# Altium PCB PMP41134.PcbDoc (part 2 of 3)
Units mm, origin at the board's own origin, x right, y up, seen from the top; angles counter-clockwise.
Board outline 252.04 x 132.61 mm, 6 copper layers (Top Layer, Layer 1, Layer 2, Layer 3, Layer 4, Bottom Layer), stack 2.208 mm thick; 221 components, 92 nets, 680 pads, 1197 vias.
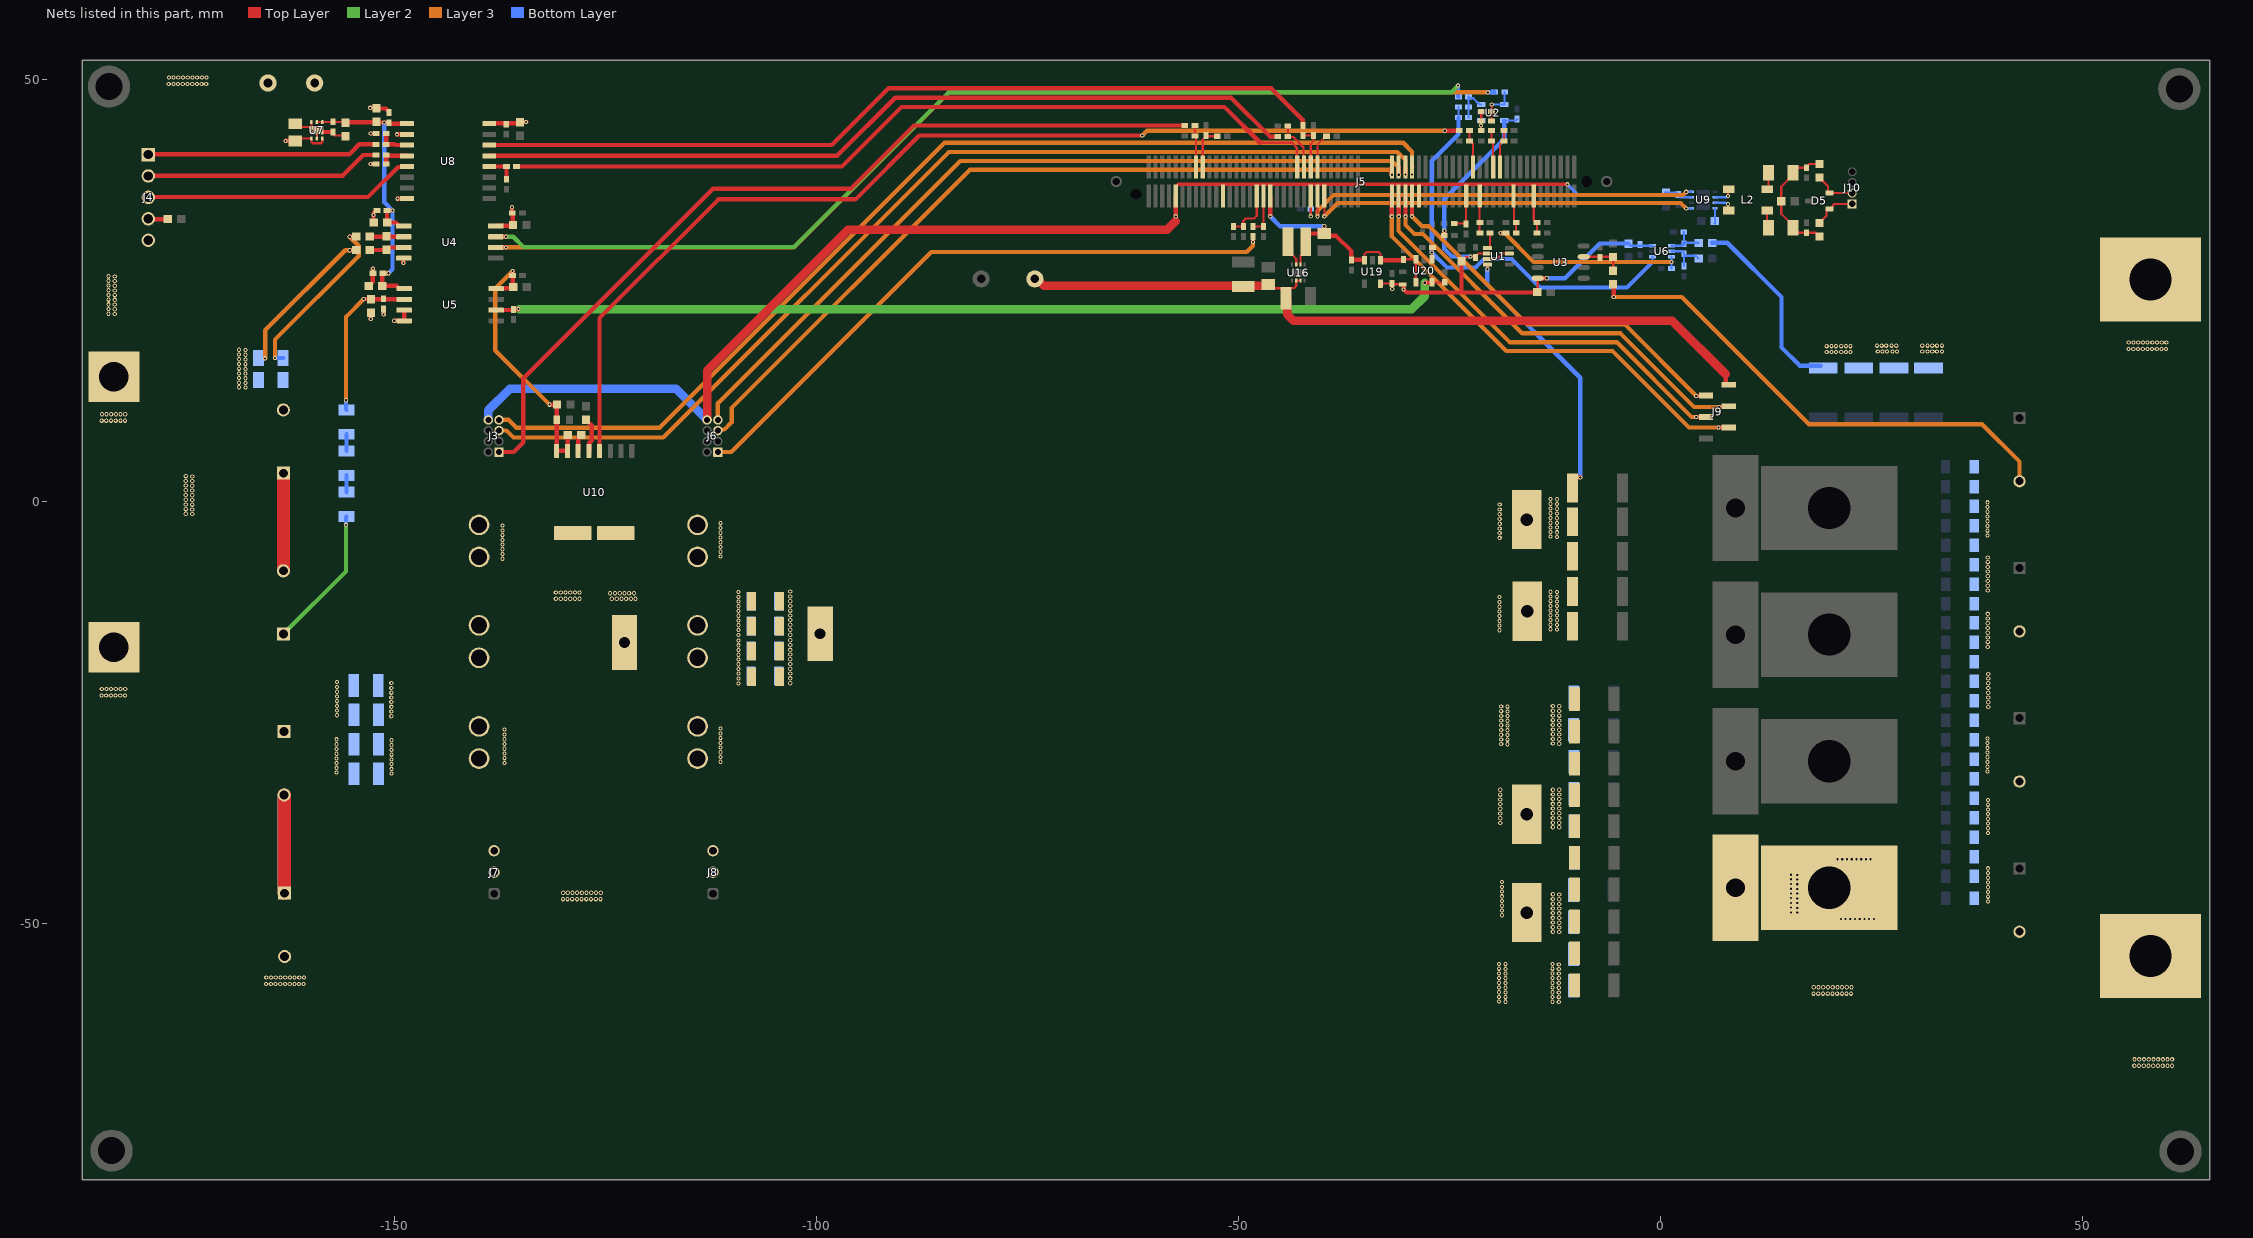
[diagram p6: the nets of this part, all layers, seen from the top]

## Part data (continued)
C128 C129: library part CMP-0009211-2, "CAP, CERM, 47 uF, 16 V, +/- 10%, X5R, 1210", Cap_Case=1210, Manufacturer=MuRata, Supplier Part Number 1=GRM32ER61C476KE15L-ND, TempCo=X5R, Tolerance_%=10%, Value1=Unknown, Value2=16V, ValueDisplayed=47uF
C131: library part CMP-0085852-1, "CAP, CERM, 22 µF, 16 V,+/- 10%, X5R, 0805", Cap_Case=0805, Manufacturer="Samsung Electro-Mechanics", TempCo=X5R, Tolerance_%=10%, Value2=16V, ValueDisplayed=22µF
C140 C141: library part CMP-0006297-2, "CAP, CERM, 0.1 uF, 50 V, +/- 10%, X7R, 0402", Alternate Manufacturer="Wurth Elektronik", Alternate PartNumber=885012205037, Cap_Case=0402, Manufacturer=TDK, Supplier Part Number 1=445-5932-1-ND, TempCo=X7R, Tolerance_%=10%, Value1="0.039064 ohm", Value2=50V, ValueDisplayed=0.1uF
C142: library part CMP-0076705-3, "CAP, CERM, 1 µF, 25 V,+/- 10%, X7R, AEC-Q200 Grade 1, 0603", Cap_Case=1.6x0.8x0.8mm, Manufacturer=TDK, Supplier Part Number 1=445-6931-1-ND, TempCo=X7R, Tolerance_%=10%, Value2=25V, ValueDisplayed=1µF
D5: library part CMP-0005919-3, "Diode, TVS, Bi, 24 V, SOT-23", Manufacturer="ON Semiconductor", Value1=350W
HV_SW1 HV_SW1 HV_SW2 HV_SW2 HVBUS HVBUS HVBUS1 HVBUS2 PGND PGND PGND1 PGND2: library part CMP-0055026-1, Manufacturer=Mill-Max, Supplier Part Number 1=0312-015153427100-ND
J3 J6: library part CMP-0097755-1, "Conn Socket Strip SKT 8 POS 1.27mm Solder ST Thru-Hole", Current_A=1A, Manufacturer=Harwin, Operating Temperature Range="-40°C to +105°C"
J4: library part CMP-0054800-1, "Header, 2.54 mm, 5x1, Gold, R/A, TH", Color=Black, Manufacturer="Wurth Elektronik", Supplier Part Number 1=732-5338-ND
J5: library part CMP-0003814-2, "C2000 controlCARD-120HSEC connector, SMT", Manufacturer=Samtec
J7 J8: library part CMP-0076709-1, "Receptacle, 2.54mm, 3x1, Gold, TH", Color=Black, Manufacturer=Mill-Max, Supplier Part Number 1=575-8014100310001000
J9: library part CMP-0054652-1, "Receptacle, 1.27mm, 6x1, Gold, SMT", Color=Black, Manufacturer="Sullins Connector Solutions", Supplier Part Number 1=S9005E-06-ND
J10: library part CMP-0054569-1, "Header, 50mil, 4x1, Gold, TH", Manufacturer="Sullins Connector Solutions", Supplier Part Number 1=S9014E-04-ND
L2: library part CMP-0062430-2, "Inductor, Ferrite, 100 uH, 0.15 A, 2 ohm, SMD", Manufacturer=TDK, Supplier Part Number 1=445-3959-1-ND, Value1="2 ohm", Value2=0.15A, ValueDisplayed=100uH
L7: library part CMP-0087867-1, "2.2µH Shielded Molded Inductor 2.4A 67mOhm Max 2-SMD", Manufacturer="Wurth Electronics"
R1 R2 R4 R7 R16 R46 R49 R50 R54: library part CMP-0015817-2, "RES, 0.0005, 1%, 2 W, 2512", Manufacturer="Stackpole Electronics Inc", Power_W=3W, TempCo=ppm/C, Tolerance_%=1%, Value2=2W, Value_Code=1L000, ValueDisplayed=0.0005
R3: library part CMP-0022438-1, "RES, 47.0 k, 1%, 0.1 W, AEC-Q200 Grade 0, 0603", Manufacturer=Vishay-Dale, Power_W=100mW, Supplier Part Number 1=541-47.0KHCT-ND, TempCo="100 ppm/C", Tolerance_%=1%, Value2=0.1W, Value_Code=47k0, ValueDisplayed=47.0k
R5 R27: library part CMP-0024062-3, "RES, 2.10 k, 0.1%, 0.1 W, 0603", Manufacturer="Yageo America", Power_W=100mW, TempCo="25 ppm/C", Tolerance_%=0.1%, Value2=0.1W, Value_Code=2k10, ValueDisplayed=2.10k
R6 R10 R34 R74: library part CMP-0025884-2, "RES, 0, 5%, 0.125 W, 0603", Manufacturer=Vishay/Beyschlag, Power_W=125mW, Supplier Part Number 1=MCT0603-0.0-ZZCT-ND, TempCo=ppm/C, Tolerance_%=5%, Value2=0.125W, Value_Code=0000, ValueDisplayed=0
R8 R9: library part CMP-0078823-1, "RES, 0.004, 1%, 1 W, AEC-Q200 Grade 0, 1206", Manufacturer=Bourns, Power_W=1W, TempCo="50 ppm/C", Tolerance_%=1%, Value_Code=4L000, ValueDisplayed=0.004
R14 R19 R21 R25: library part CMP-0026739-1, "RES, 4.70 k, 1%, 0.0625 W, 0402", Manufacturer="Yageo America", Power_W=62.5mW, Supplier Part Number 1=311-4.7KLRCT-ND, TempCo="100 ppm/C", Tolerance_%=1%, Value2=0.0625W, Value_Code=4k70, ValueDisplayed=4.70k
R15 R17 R20: library part CMP-0017437-1, "RES, 200 k, 1%, 0.25 W, 1206", Manufacturer=Panasonic, Power_W=250mW, Supplier Part Number 1=P200KFCT-ND, TempCo="100 ppm/C", Tolerance_%=1%, Value2=0.25W, Value_Code=200k
R18 R24 R70 R72: library part CMP-0022003-4, "RES, 10.0, 1%, 0.1 W, AEC-Q200 Grade 0, 0603", Manufacturer=Vishay-Dale, Power_W=100mW, Supplier Part Number 1=541-10.0HCT-ND, TempCo="100 ppm/C", Tolerance_%=1%, Value2=0.1W, Value_Code=10R0, ValueDisplayed=10.0
R22 R23 R28 R29 R31 R76 R84 R85 R86 R89 R97 R98 R101 R102 R104 R105: library part CMP-0025951-1, "RES, 100, 1%, 0.063 W, 0402", Manufacturer=Vishay-Dale, Power_W=63mW, Supplier Part Number 1=541-100LCT-ND, TempCo="100 ppm/C", Tolerance_%=1%, Value2=0.063W, Value_Code=100R, ValueDisplayed=100
R26 R30: library part CMP-0027004-2, "RES, 0, 5%, 0.063 W, 0402", Manufacturer="Yageo America", Power_W=63mW, Supplier Part Number 1=311-0.0JRCT-ND, TempCo="200 ppm/C", Tolerance_%=5%, Value2=0.063W, Value_Code=0000, ValueDisplayed=0
R32 R35: library part CMP-0025885-5, "RES, 0, 5%, 0.1 W, 0603", Manufacturer=Yageo, Power_W=100mW, Supplier Part Number 1=311-0.0GRCT-ND, TempCo="200 ppm/C", Tolerance_%=5%, Value2=0.1W, Value_Code=0000, ValueDisplayed=0
R33 R36: library part CMP-0018709-3, "RES, 60, 10%, 0.25 W, AEC-Q200 Grade 0, 1206", Manufacturer=Vishay-Dale, Power_W=250mW, Supplier Part Number 1=CRCW120660R0KNEAIF-ND, TempCo="200 ppm/C", Tolerance_%=10%, Value2=0.25W, Value_Code=60R0, ValueDisplayed=60
R67: library part CMP-0025958-3, "RES, 10.0 k, 1%, 0.063 W, AEC-Q200 Grade 0, 0402", Manufacturer=Vishay-Dale, PartNumber=CRCW040210K0FKED, Power_W=63mW, Supplier Part Number 1=541-10.0KLCT-ND, TempCo="100 ppm/C", Tolerance_%=1%, Value2=0.063W, Value_Code=10k0, ValueDisplayed=10.0k
RT1: library part CMP-0084566-1, "Thermistor, DEC0002A (X1SON-2)", Alternate Manufacturer="Texas Instruments", Alternate PartNumber=TMP6131DECT
U1: library part CMP-0093650-2, "-4-V to 110-V, Bidirectional, Ultra-Precise Current Sense Amplifier With Enhanced PWM Rejection", Input Bias Current=40uA, Input Offset Voltage=0.002mV, Manufacturer="Texas Instruments", Max Supply Voltage=20V, Min Supply Voltage=2.7V, Nominal Supply Current=2.5mA, Operating Temperature Range="-40°C to +125°C", Voltage Gain=0.1V/mV
U2: library part CMP-0040888-1, "Precision, 20 MHz, 0.9 pA Ib, RRIO, CMOS Operational Amplifier, 1.8 to 5.5 V, -40 to 125 degC, 5-pin SOT23 (DBV5), Green (RoHS & no Sb/Br)", Manufacturer="Texas Instruments", Total Supply Voltage(Max)(+5V is 5, +/-5V is 10)=5.5, Total Supply Voltage(Min)(+5V is 5, +/-5V is 10)=1.8
U3: library part CMP-0013007-4, "10-MHz, Low-Noise, RRIO, CMOS Operational Amplifier for Cost-Sensitive Systems, D0008A (SOIC-8)", Alternate Manufacturer="Texas Instruments", Alternate PartNumber=TLV9062ID, Operating Temperature Range="-40 to 125 C", Rating=Catalog
U4: library part CMP-0080587-1, "Precision Reinforced Isolated Amplifier for Current Sensing, DWV0008A (SOIC-8)", Alternate Manufacturer="Texas Instruments"
U5: library part CMP-0122957-1, "Automotive, Precision, 2-V Input, Basic and Reinforced Isolated Amplifiers With Single-Ended, Ratiometric Output", Input Bias Current=0.0035uA, Input Offset Voltage=0.4mV, Manufacturer="Texas Instruments", Max Supply Voltage=5.5V, Min Supply Voltage=3V, Operating Temperature Range="-40°C to +125°C", Output Current Per Channel=14mA
U6: library part CMP-0037966-3, "26-V, Bi-Directional, Zero-Drift, Low- or High-Side, Voltage Output Current Shunt Monitor, DCK0006A (SOT-SC70-6)", Manufacturer="Texas Instruments", Operating Temperature Range="-40 to 125 C", Quiescent Current (+/-)(Typ)(mA)=0.065, Rating=Catalog
U7: library part CMP-0090734-1, "Linear Voltage Regulator IC  1 Output  1A 6-WSON (2x2)", Digikey Part Number=296-TLV76733DRVTCT-ND, Dropout Voltage=0.9V, Manufacturer="Texas Instruments", Max Supply Voltage=16V, Min Supply Voltage=2.5V, Mouser Part Number=595-TLV76733DRVT, Nominal Supply Current=60uA, Operating Temperature Range="-40°C to +125°C", Output Voltage=3.3V
U8: library part CMP-0065839-3, "5.7 kVrms, 100 Mbps, Reinforced 4-Channel 2/2 Digital Isolator, DW0016B (SOIC-16)", Alternate Manufacturer="Texas Instruments", Alternate PartNumber=ISO7842DW, Operating Temperature Range="-55 to 125 C", Rating=Catalog
U9: library part CMP-0065181-3, "Automotive Fault Protected CAN Transceiver With Flexible Data-Rate, DRB0008F (VSON-8)", Alternate Manufacturer="Texas Instruments", Alternate PartNumber=TCAN1042HDRBTQ1, Operating Temperature Range="-55 to 125 C", Rating=Automotive
U10: library part CMP-0097985-1, Manufacturer="Texas Instruments", Operating Temperature Range=to
U16: library part CMP-0037791-2, "Buck Step Down Regulator with 3 to 17 V Input and 5 V Output, -40 to 85 degC, 8-Pin WSON (DSG), Green (RoHS & no Sb/Br)", Manufacturer="Texas Instruments", Rating=Catalog, Switch Current Limit(Typ)(A)=1.8
U19: library part CMP-0073750-1, "Capacitor-Free, 150-mA, LDO Regulator w/ Foldback Current Limit, DBV0005A (SOT-23-5)", Alternate Manufacturer="Texas Instruments"
U20: library part CMP-0066190-1, "Low-Drift, Low-Power, Dual-Output VREF and VREF/2 Voltage Reference, DDC0005A (SOT-23-T-5)", Alternate Manufacturer="Texas Instruments", Alternate PartNumber=REF2033AIDDCT

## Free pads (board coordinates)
  rect 6x6 hole 3.5: 2(-183.261,-17.221) 2(-183.261,14.835)
  rect 3x6.5 hole 1.3 slot 5 at 90 deg: 2(-122.777,-16.645) 2(-99.593,-15.621)
  rect 3.5x7 hole 1.5 slot 5.4 at 90 deg: 2(-15.9,-48.666) 2(-15.9,-37) 2(-15.9,-2.1) 2(-15.85,-12.954)
  rect 5.4x12.6 hole 2.2 square: 2(8.839,-45.723) 2(8.839,-30.723) 2(8.839,-15.723) 2(8.839,-0.723)
  rect 16.2x10 hole 5: 2(19.94,-45.723) 2(19.94,-30.723) 2(19.94,-15.723) 2(19.94,-0.723)
  rect 12x10 hole 5: 2(57.988,-53.797) 2(57.988,26.342)
  round 5 hole 3.2: 3(-183.845,49.2) 3(-183.54,-76.86) 3(61.417,48.92) 3(61.57,-76.937)

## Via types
v1: diameter 0.5, hole 0.254, Top Layer to Bottom Layer, tented both sides, 1189 vias
v2: diameter 0.5, hole 0.2, Top Layer to Bottom Layer, 8 vias

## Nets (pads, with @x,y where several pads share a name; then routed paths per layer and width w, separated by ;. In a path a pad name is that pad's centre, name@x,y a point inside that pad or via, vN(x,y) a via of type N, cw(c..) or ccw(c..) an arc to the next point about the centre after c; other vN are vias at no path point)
1V65: C42.2 C151.1 R25.1 U1.3 U1.7 U6.1 U20.1 | length 53.4
  Top Layer w0.254: U20.1@-27.136,28.748 -27.136,30.073 C151.1@-27.071,30.138 ; U1.7@-20.557,28.763 v1(-19.751,28.763) -19.507,28.763 -18.857,29.413 U1.3@-17.957,29.413
  Bottom Layer w0.254: C42.2@-23.986,45.517 R25.1@-23.986,46.8 ; -1.009,28.417 U6.1@-1.009,29.042
  Bottom Layer w0.508: C42.2@-23.986,45.517 -23.986,43.553 -27.153,40.386 -27.153,29.56 -25.352,27.759 -21.951,27.759 -20.948,28.763 v1(-19.751,28.763) -17.703,28.763 -14.34,25.4 -4.026,25.4 -1.009,28.417
  other v1: -27.153,29.54
3.3Vp: C30.1 C31.1 C35.1 C47.1 C75.2 C76.1 C86.1 C141.1 U4.1 U5.1 U7.1 U7.2 U8.1 | length 38.5
  Top Layer w0.254: U7.2@-159.211,44.998 U7.1@-158.561,44.998 -155.902,44.998 C75.2@-155.822,44.918
  Top Layer w0.508: C75.2@-155.822,44.918 -155.769,44.97 -152.223,44.97 C86.1@-152.171,45.022 -152.1,44.951 v1(-151.237,44.951) -150.723,44.951 C141.1@-150.687,44.915 -150.583,44.811 U8.1@-148.552,44.811 ; v1(-150.735,27.086) C35.1@-151.385,27.086 -151.439,27.086 -151.485,27.04 C47.1@-151.485,25.601 -149.816,25.601 -149.479,25.264 U5.1@-148.879,25.264 ; v1(-150.253,34.526) C31.1@-150.903,34.526 C30.1@-150.903,33.109 -149.872,33.109 -149.574,32.812 -149.574,32.727 -149.528,32.681 U4.1@-148.928,32.681
  Bottom Layer w0.508: v1(-151.237,44.951) -151.237,35.511 v1(-150.253,34.526) -150.253,27.568 v1(-150.735,27.086)
3.3Vref: C74.2 C150.1 U5.6 U20.5 | length 114.6
  Top Layer w0.254: U20.5@-27.136,25.998 -25.625,25.998 C150.1@-25.61,26.013
  Top Layer w0.508: U5.6@-137.979,22.724 -135.982,22.724 -135.936,22.77 C74.2@-135.936,22.805 -135.906,22.835 v1(-135.331,22.835) ; v1(-27.978,25.957) -27.177,25.957 U20.5@-27.136,25.998
  Layer 2 w1.016: v1@-135.23,22.835 -29.515,22.835 -27.978,24.371 v1(-27.978,25.957)
3.3Vs: C3.1 C20.1 C24.1 C26.1 C32.1 C33.1 C34.1 C38.1 C48.1 C87.2 C92.2 C93.2 C111.1 C140.2 C142.1 C143.1 R10.2 R67.1 U1.6 U2.5 U3.8 U4.8 U5.8 U6.3 U8.16 U10.9 U10.10 U19.5 | length 109.5
  Top Layer w0.254: U19.5@-33.228,25.864 -31.838,25.864 C143.1@-31.834,25.869 C143.1@-31.834,25.779 ; v1(-31.834,25.219) C143.1@-31.834,25.779 ; C142.1@-30.58,25.779 C143.1@-31.834,25.779 ; C20.1@-23.62,28.509 -23.62,28.534 -23.272,28.882 -23.247,28.882 -23.119,29.011 -22.602,29.011 v1(-22.555,29.058) -22.108,29.058 C24.1@-22.011,28.96 ; C24.1@-22.011,29.06 -21.838,29.233 -21.815,29.233 -21.635,29.413 U1.6@-20.557,29.413 ; C3.1@-14.662,24.858 -14.596,24.925 U3.8@-14.596,26.496
  Top Layer w0.508: U8.16@-138.802,44.811 -138.756,44.857 -135.251,44.857 C87.2@-135.157,44.951 -135.11,44.998 v1(-134.432,44.998) ; U4.8@-138.028,32.681 -137.982,32.727 -136.055,32.727 C32.1@-135.985,32.798 -136.029,32.842 -136.029,34.182 C33.1@-136.073,34.226 -136.093,34.247 v1(-136.093,34.9) ; U5.8@-137.979,25.264 -137.933,25.31 -136.101,25.31 C48.1@-135.979,25.432 -136.019,25.472 -136.019,26.756 -136.029,26.766 v1(-136.029,27.346) ; v1(-131.653,11.518) C26.1@-130.772,11.518 ; C111.1@-130.803,9.718 C26.1@-130.803,11.487 ; C111.1@-130.664,9.715 -130.664,9.61 -130.81,9.464 U10.10@-130.81,6.043 U10.9@-129.54,6.043 -129.502,6.082 -129.502,7.887 R10.2@-129.464,7.925 ; C142.1@-30.464,25.754 -30.48,25.754 v1(-30.48,25.171) -30.121,24.813 -23.62,24.813 ; R67.1@-25.657,31.606 v1(-25.654,32.114) ; C20.1@-23.62,28.509 -23.62,24.813 ; C3.1@-14.662,24.858 -14.708,24.813 -23.62,24.813 ; U3.8@-14.596,26.496 v1(-13.519,26.496)
  Layer 3 w0.508: v1(-136.029,27.346) -136.909,26.465 -138.1,25.275 -138.1,17.966 v1(-131.653,11.518)
  Bottom Layer w0.254: U2.5@-18.546,45.178 -17.198,45.178 C34.1@-17.026,45.35 ; C93.2@-3.866,30.605 -3.603,30.342 U6.3@-1.009,30.342
  Bottom Layer w0.508: v1(-22.555,29.058) -24.761,29.058 -25.654,29.951 v1(-25.654,32.114) -25.654,35.901 -18.546,43.009 U2.5@-18.546,45.178 ; v1(-13.519,26.496) -11.357,26.496 -7.249,30.605 C93.2@-3.866,30.605
5Vs: C95.1 C102.1 C131.1 C144.1 C149.1 J3.8 J5.48 J5.84 J5.98 J5.112 J6.8 L7.2 U9.3 U16.6 U19.1 U19.3 U20.3 U20.4 | length 202.8
  Top Layer w0.254: U16.6@-42.699,28.119 -42.699,29.136 -42.075,29.76 L7.2@-42.075,29.832 ; L7.2@-42.075,30.81 L7.2@-42.075,29.832 ; L7.2@-41.552,29.309 L7.2@-42.075,29.832 ; U19.3@-35.157,28.643 U19.3@-35.128,28.614 ; U19.3@-35.128,28.623 -35.128,29.339 -34.86,29.608 -33.44,29.608 -33.228,29.396 U19.1@-33.228,28.614 ; C149.1@-30.569,28.614 C149.1@-30.473,28.71 -30.436,28.748 U20.3@-29.036,28.748 U20.4@-29.036,25.998
  Top Layer w0.381: v1@-57.469,33.83 v1(-57.467,33.828) ; J5.112@-57.469,36.246 J5.112@-57.471,36.248 -57.471,37.32 -57.173,37.617 -51.871,37.617 ; J5.98@-51.875,36.252 -51.871,37.617 ; J5.84@-46.271,36.248 J5.84@-46.271,37.437 ; J5.48@-28.675,36.252 -28.675,37.617 ; v1(-11.071,37.617) -28.675,37.617 ; -51.871,37.617 -28.675,37.617
  Top Layer w0.508: v1@-57.469,33.83 J5.112@-57.469,36.246 ; -57.467,33.27 v1(-57.467,33.828) ; J5.98@-51.875,36.252 J5.98@-51.871,36.248 ; v1(-46.275,33.828) -46.275,36.244 J5.84@-46.271,36.248 ; L7.2@-42.075,30.81 -42.075,31.399 -41.679,31.795 C131.1@-40.05,31.795 ; C131.1@-40.431,32.176 C131.1@-40.05,31.795 ; C131.1@-39.885,31.981 v1(-39.885,32.659) ; U19.3@-35.128,28.614 -35.128,28.623 -35.174,28.669 C144.1@-36.671,28.669 -36.671,29.706 -38.481,31.517 -39.606,31.517 C131.1@-39.885,31.795 C131.1@-40.05,31.795 ; U19.1@-33.228,28.614 C149.1@-30.569,28.614 ; J5.48@-28.675,36.252 J5.48@-28.671,36.248
  Top Layer w1.016: J6.8@-112.991,9.728 -112.991,15.541 -96.299,32.233 -58.504,32.233 -57.467,33.27
  Bottom Layer w0.254: C102.1@0.58,36.615 1.88,36.615 2.053,36.442 C95.1@2.053,36.415 2.053,36.315 2.279,36.089 U9.3@3.627,36.089
  Bottom Layer w0.381: v1(-11.071,37.617) -9.852,36.398 0.363,36.398 C102.1@0.58,36.615
  Bottom Layer w0.508: v1(-46.275,33.828) -45.106,32.659 v1(-39.885,32.659)
  Bottom Layer w1.016: J3.8@-138.913,9.728 -138.913,10.846 -136.373,13.386 -116.649,13.386 J6.8@-112.991,9.728
12Vp: 3.1 C77.1 J7.3 J8.3 U7.4 U7.6 | length 5.4
  Top Layer w0.254: C77.1@-161.654,42.62 -161.226,43.048 U7.4@-159.861,43.048 -159.861,42.637 -159.712,42.488 -158.71,42.488 -158.584,42.614 -158.584,43.025 U7.6@-158.561,43.048
  Top Layer w0.508: v1(-162.922,42.767) -161.802,42.767 C77.1@-161.786,42.752
12Vs: 4.1 C128.2 C129.2 C130.1 J9.1 U16.2 U16.3 | length 92.4
  Top Layer w0.254: C130.1@-46.522,25.815 -46.014,25.307 -44.948,25.307 C128.2@-44.425,24.784 ; C128.2@-44.425,24.113 C128.2@-44.425,24.784 ; U16.3@-42.699,26.219 U16.2@-43.199,26.219 -43.199,25.588 -43.45,25.336 -43.902,25.336 -44.425,24.813 C128.2@-44.425,24.784
  Top Layer w0.508: 7.671,15.113 7.671,13.938 7.767,13.842 J9.1@8.039,13.842
  Top Layer w0.762: C130.1@-46.75,25.527 C130.1@-46.522,25.755
  Top Layer w1.016: 4.1@-74.168,26.416 -73.915,26.416 -73.087,25.588 C130.1@-46.75,25.588 ; C128.2@-44.425,24.113 -44.283,23.971 -44.283,22.225 -43.521,21.463 1.321,21.463 7.671,15.113
48Vo+: C49.1 C50.1 C51.1 C52.1 C53.1 C54.1 C55.1 C56.1 C57.1 C58.1 C59.2 C60.1 C61.2 C62.2 C63.2 C64.1 C65.1 C66.1 C67.1 C68.1 C69.1 C70.1 C71.1 C72.1 C114.1 C115.1 C116.1 pad.2@8.839,-45.723 pad.2@19.94,-45.723 pad.2@57.988,-53.797 R3.2 | length 60
  Top Layer w0.508: R3.2@-5.649,25.804 -5.594,25.749 v1(-5.594,24.282)
  Layer 3 w0.508: v1(-5.594,24.282) 2.464,24.282 17.54,9.207 38.044,9.207 42.485,4.766 C62.2@42.485,2.448
  other v1: 56.086,-66.802 56.645,-66.802 57.203,-66.802 57.762,-66.802 58.321,-66.802 58.88,-66.802 59.439,-66.802 59.997,-66.802 60.531,-66.802 56.111,-66.04 56.67,-66.04 57.229,-66.04 57.788,-66.04 58.346,-66.04 58.905,-66.04 59.464,-66.04 60.023,-66.04 60.563,-66.04 18.085,-58.258 18.644,-58.258 19.202,-58.258 19.761,-58.258 20.32,-58.258 20.879,-58.258 21.438,-58.258 21.996,-58.258 22.53,-58.258 18.11,-57.496 18.669,-57.496 19.228,-57.496 19.787,-57.496 20.345,-57.496 20.904,-57.496 21.463,-57.496 22.022,-57.496 22.562,-57.496 21.318,-49.403 21.877,-49.403 22.436,-49.403 22.995,-49.403 23.554,-49.403 24.113,-49.403 24.672,-49.403 25.231,-49.403 16.153,-48.648 15.391,-48.622 16.153,-48.089 15.391,-48.064 16.153,-47.53 15.391,-47.505 38.745,-47.325 16.153,-46.971 15.391,-46.946 38.745,-46.766 16.153,-46.413 15.391,-46.387 38.745,-46.207 16.153,-45.854 15.391,-45.828 38.745,-45.648 16.153,-45.295 15.391,-45.27 38.745,-45.089 16.153,-44.736 15.391,-44.711 38.745,-44.53 16.153,-44.203 15.391,-44.17 38.745,-43.971 38.745,-43.412 20.931,-42.337 21.49,-42.337 22.049,-42.337 22.608,-42.337 23.167,-42.337 23.726,-42.337 24.285,-42.337 24.844,-42.337 38.745,-39.222 38.745,-38.663 38.745,-38.104 38.745,-37.545 38.745,-36.986 38.745,-36.427 38.745,-35.868 38.745,-35.309 38.702,-31.932 38.702,-31.373 38.702,-30.814 38.702,-30.255 38.702,-29.696 38.702,-29.137 38.702,-28.578 38.702,-28.019 38.774,-24.288 38.774,-23.729 38.774,-23.17 38.774,-22.611 38.774,-22.052 38.774,-21.493 38.774,-20.934 38.774,-20.375 38.719,-17.175 38.719,-16.616 38.719,-16.057 38.719,-15.498 38.719,-14.939 38.719,-14.38 38.719,-13.821 38.719,-13.262 38.719,-10.494 38.719,-9.935 38.719,-9.376 38.719,-8.817 38.719,-8.258 38.719,-7.699 38.719,-7.14 38.719,-6.581 38.676,-3.967 38.676,-3.408 38.676,-2.849 38.676,-2.29 38.676,-1.731 38.676,-1.172 38.676,-0.613 38.676,-0.054
48Vo-: pad.2@57.988,26.342 R46.2 R49.2 R50.2 R54.2 R72.1 | length 22.4
  Bottom Layer w0.508: R72.1@6.062,30.693 7.864,30.693 14.281,24.276 14.281,18.301 16.459,16.129 R46.2@18.932,16.129
  other v1: 19.634,17.755 20.193,17.755 20.726,17.755 21.361,17.755 21.92,17.755 22.454,17.755 25.699,17.816 26.258,17.816 26.791,17.816 27.426,17.816 27.985,17.816 30.959,17.816 31.594,17.816 32.153,17.816 32.686,17.816 33.311,17.816 55.397,18.11 55.956,18.11 56.515,18.11 57.074,18.11 57.633,18.11 58.191,18.11 58.75,18.11 59.309,18.11 59.842,18.11 19.634,18.447 20.193,18.447 20.726,18.447 21.361,18.447 21.92,18.447 22.454,18.447 25.591,18.508 26.15,18.508 26.683,18.508 27.318,18.508 27.877,18.508 30.959,18.508 31.594,18.508 32.153,18.508 32.686,18.508 33.311,18.508 55.423,18.872 55.982,18.872 56.54,18.872 57.099,18.872 57.658,18.872 58.217,18.872 58.776,18.872 59.334,18.872 59.875,18.872
Bot_ZVD1: J3.1 R102.1 | length 101.7
  Top Layer w0.508: J3.1@-137.643,5.918 -135.906,5.918 -134.759,7.066 -134.759,14.644 -112.319,37.084 -95.987,37.084 -88.491,44.58 R102.1@-56.399,44.58
Bot_ZVD2: J6.1 R97.1 | length 74.6
  Top Layer w0.508: v1(-48.321,30.784) R97.1@-48.321,31.434
  Layer 3 w0.508: J6.1@-111.721,5.918 -110.121,5.918 -86.448,29.591 -49.073,29.591 -48.321,30.343 v1(-48.321,30.784)
CAN_RX: J5.70 U9.4 | length 48.4
  Top Layer w0.254: v1(-40.671,33.828) J5.70@-40.671,36.248
  Layer 3 w0.508: v1(-40.671,33.828) -40.671,34.462 -38.786,36.347 2.616,36.347 v1(2.997,36.728)
  Bottom Layer w0.254: v1@2.95,36.775 v1(2.997,36.728) 3.003,36.734 3.621,36.734 U9.4@3.627,36.739
CAN_TX: J5.68 U9.1 | length 46.9
  Top Layer w0.254: v1(-39.871,33.828) J5.68@-39.871,36.248
  Layer 3 w0.508: v1(-39.871,33.828) -38.291,35.408 2.337,35.408 v1(2.997,34.747)
  Bottom Layer w0.254: v1(2.997,34.747) 3.018,34.768 3.606,34.768 U9.1@3.627,34.789
CANH: D5.1 J10.1 R32.2 | length 5.3
  Top Layer w0.254: R32.2@18.771,33.041 18.771,33.066 19.119,33.414 19.144,33.414 19.612,33.883 19.612,34.54 19.783,34.712 20.158,34.712 20.329,34.883 20.329,35.07 20.565,35.306 J10.1@22.657,35.306
CANL: D5.2 J10.2 R35.2 | length 5
  Top Layer w0.254: R35.2@18.771,38.429 18.771,38.404 19.119,38.056 19.144,38.056 19.783,37.417 19.783,36.783 19.954,36.612 D5.2@19.971,36.612 19.988,36.594 22.639,36.594 J10.2@22.657,36.576
HV_PWM1H: J3.7 J5.49 | length 126.6
  Top Layer w0.508: v1(-29.475,38.775) -29.475,39.644 J5.49@-29.471,39.648
  Layer 3 w0.508: J3.7@-137.643,9.728 -136.525,9.728 -135.585,8.788 -118.618,8.788 -84.861,42.545 -30.531,42.545 -29.475,41.489 v1(-29.475,38.775)
HV_PWM1L: J3.5 J5.51 | length 124.7
  Top Layer w0.508: J5.51@-30.271,39.648 -30.267,39.644 v1(-30.267,38.778)
  Layer 3 w0.508: J3.5@-137.643,8.458 -136.774,8.458 -135.936,7.62 -118.186,7.62 -84.353,41.453 -31.232,41.453 -30.267,40.488 v1(-30.267,38.778)
HV_PWM2H: J5.53 J6.7 | length 96.5
  Top Layer w0.508: J5.53@-31.071,39.648 -31.067,39.644 -31.067,38.763 v1(-31.064,38.76)
  Layer 3 w0.508: J6.7@-111.721,9.728 -111.721,11.672 -83.007,40.386 -31.852,40.386 -31.064,39.599 v1(-31.064,38.76)
HV_PWM2L: J5.55 J6.5 | length 94.9
  Top Layer w0.508: J5.55@-31.877,38.76 v1(-31.875,38.763) -31.875,39.644 J5.55@-31.871,39.648
  Layer 3 w0.508: J6.5@-111.721,8.458 -111.604,8.575 -110.944,8.575 -110.084,9.436 -110.084,11.125 -81.866,39.342 -32.172,39.342 -31.875,39.045 v1(-31.875,38.763)
HV_SW1: HV_SW1.1 U10.1
  other v1: -130.912,-11.481 -130.327,-11.481 -129.769,-11.481 -129.21,-11.481 -128.651,-11.481 -128.092,-11.481 -130.912,-10.75 -130.327,-10.75 -129.769,-10.75 -129.21,-10.75 -128.651,-10.75 -128.092,-10.75
HV_SW2: C1.1 C2.1 C4.1 C7.1 C14.1 C17.1 C22.1 C28.1 HV_SW2.1
  other v1: -109.271,-21.515 -109.271,-20.93 -109.271,-20.346 -109.271,-19.787 -109.271,-19.229 -109.271,-18.67 -109.271,-18.111 -109.271,-17.552 -109.271,-16.993 -109.271,-16.409 -109.271,-15.774 -109.271,-15.19 -109.271,-14.606 -109.271,-14.047 -109.271,-13.488 -109.271,-12.929 -109.271,-12.371 -109.271,-11.812 -109.271,-11.253 -109.271,-10.669
HVBUS: C8.1 C11.1 C12.1 C13.1 C101.1 C105.1 HVBUS1.1 HVBUS2.1 HVBUS.1 pad.2@-183.261,-17.221 R15.2 | length 17
  Layer 2 w0.508: C8.1@-163.195,-15.663 -155.778,-8.246 v1(-155.778,-2.718)
  Bottom Layer w0.508: v1(-155.778,-2.718) -155.778,-1.819 R15.2@-155.716,-1.757
  other v1: -156.896,-32.065 -156.896,-31.506 -156.896,-30.947 -156.896,-30.388 -156.896,-29.83 -156.896,-29.271 -156.896,-28.712 -156.896,-28.128 -156.82,-25.283 -156.82,-24.724 -156.82,-24.165 -156.82,-23.607 -156.82,-23.048 -184.724,-22.922 -184.184,-22.922 -183.625,-22.922 -183.066,-22.922 -182.507,-22.922 -181.948,-22.922 -156.82,-22.489 -184.692,-22.16 -184.158,-22.16 -183.599,-22.16 -183.041,-22.16 -182.482,-22.16 -181.923,-22.16 -156.82,-21.93 -156.82,-21.346 -137.215,-6.735 -111.404,-6.458 -137.215,-6.177 -111.404,-5.899 -137.215,-5.618 -111.404,-5.34 -137.215,-5.059 -111.404,-4.782 -137.215,-4.5 -111.404,-4.223 -137.215,-3.941 -111.404,-3.664 -137.215,-3.383 -111.404,-3.105 -137.215,-2.798 -111.404,-2.521
ISNS_PRI: C25.1 R14.2 R84.1 U2.1 | length 2.9
  Top Layer w0.254: C25.1@-21.283,46.228 -21.283,45.157 R14.2@-21.271,45.145 -21.306,45.11 -21.306,44.009 R84.1@-21.271,43.974
  Bottom Layer w0.254: v1(-21.311,44.581) -21.311,45.163 U2.1@-21.296,45.178
ISNS_PRI_TANK: R86.1 U10.6 | length 126.8
  Top Layer w0.508: U10.6@-125.73,6.043 -125.73,21.768 -111.658,35.839 -95.428,35.839 -87.859,43.409 v1(-61.443,43.409) ; v1(-25.61,43.974) R86.1@-23.883,43.974
  Layer 3 w0.508: v1(-61.443,43.409) -60.877,43.974 v1(-25.61,43.974)
ISNS_SEC: C98.1 R23.2 U6.6 | length 23.7
  Top Layer w0.254: v1(-18.996,31.839) R23.2@-18.346,31.839
  Layer 3 w0.508: v1(-18.996,31.839) -18.504,31.839 -15.082,28.417 v1(1.257,28.417)
  Bottom Layer w0.254: v1@1.241,28.417 U6.6@1.241,29.042 ; C98.1@1.253,27.639 1.257,27.643 v1(1.257,28.417)
ISNS_SEC_TANK: R76.2 U1.5 | length 2
  Top Layer w0.254: U1.5@-20.557,30.063 -20.343,30.063 -20.245,30.161 R76.2@-20.245,31.851
LV_PWM1H: J5.50 J9.2 | length 46.1
  Top Layer w0.508: v1(-29.475,33.828) -29.475,36.244 J5.50@-29.471,36.248 ; v1(4.191,12.548) 5.314,12.548 J9.2@5.339,12.572
  Layer 3 w0.508: v1(-29.475,33.828) -28.306,32.659 -27.479,32.659 -15.825,21.006 -4.267,21.006 v1(4.191,12.548)
LV_PWM1L: J5.52 J9.3 | length 50.7
  Top Layer w0.508: J5.52@-30.271,36.248 -30.267,36.244 v1(-30.267,33.828) ; v1(6.858,11.252) 7.967,11.252 J9.3@8.05,11.335
  Layer 3 w0.508: v1(-30.267,33.828) -30.267,32.799 -29.193,31.725 -28.189,31.725 -16.429,19.964 -4.775,19.964 3.937,11.252 v1(6.858,11.252)
LV_PWM2H: J5.54 J9.4 | length 49.7
  Top Layer w0.508: J5.54@-31.071,36.248 -31.067,36.244 -31.067,33.83 v1(-31.064,33.828) ; v1(4.191,10.058) 5.313,10.058 J9.4@5.339,10.032
  Layer 3 w0.508: v1@-31.09,33.802 -31.09,32.094 -17.919,18.923 -5.232,18.923 3.632,10.058 v1(4.191,10.058)
  Bottom Layer w0.508: v1@-31.09,33.802 v1(-31.064,33.828)
LV_PWM2L: J5.56 J9.5 | length 54.1
  Top Layer w0.508: v1(-31.875,33.828) -31.875,36.244 J5.56@-31.871,36.248 ; v1(6.807,8.814) 7.988,8.814 J9.5@8.039,8.762
  Layer 3 w0.508: v1(-31.875,33.828) -31.875,31.443 -18.313,17.882 -5.74,17.882 3.327,8.814 v1(6.807,8.814)
NetC1_2: C1.2 C2.2 C4.2 C7.2 C14.2 C17.2 C22.2 C28.2 pad.2@-99.593,-15.621
  other v1: -103.149,-21.488 -103.149,-20.904 -103.149,-20.32 -103.149,-19.761 -103.149,-19.202 -103.149,-18.644 -103.149,-18.085 -103.149,-17.526 -103.149,-16.967 -103.149,-16.383 -103.149,-15.731 -103.149,-15.147 -103.149,-14.563 -103.149,-14.004 -103.149,-13.445 -103.149,-12.886 -103.149,-12.328 -103.149,-11.769 -103.149,-11.21 -103.149,-10.626
NetC5_1: C5.1 C6.1 C9.1 C10.1 C15.1 C16.1 C19.1 C21.1 C23.1 C27.1 C29.1 C36.1 C37.1 C39.1 C41.1 C43.1 C44.1 C45.1 C46.1 C113.1 pad.2@-15.9,-37 pad.2@-15.9,-48.666
  other v1: -12.09,-59.233 -18.415,-59.215 -12.852,-59.207 -19.177,-59.182 -18.415,-58.674 -12.09,-58.674 -19.177,-58.649 -12.852,-58.649 -18.415,-58.115 -12.09,-58.115 -19.177,-58.09 -12.852,-58.09 -18.415,-57.556 -12.09,-57.556 -19.177,-57.531 -12.852,-57.531 -18.415,-56.998 -12.09,-56.998 -19.177,-56.972 -12.852,-56.972 -18.415,-56.439 -12.09,-56.439 -19.177,-56.413 -12.852,-56.413 -18.415,-55.88 -12.09,-55.88 -19.177,-55.855 -12.852,-55.855 -18.415,-55.321 -12.09,-55.321 -19.177,-55.296 -12.852,-55.296 -12.09,-54.788 -18.415,-54.762 -12.852,-54.755 -19.177,-54.737 -12.04,-50.96 -12.802,-50.927 -12.04,-50.419 -12.802,-50.394 -12.04,-49.86 -12.802,-49.835 -12.04,-49.301 -12.802,-49.276 -18.831,-48.965 -12.04,-48.743 -12.802,-48.717 -18.831,-48.406 -12.04,-48.184 -12.802,-48.158 -18.831,-47.847 -12.04,-47.625 -12.802,-47.6 -18.831,-47.288 -12.04,-47.066 -12.802,-47.041 -18.831,-46.729 -12.04,-46.507 -12.802,-46.482 -18.831,-46.171 -18.831,-45.612 -18.831,-45.028 -12.04,-38.546 -12.802,-38.539 -19.034,-38.035 -12.802,-38.006 -12.04,-38.006 -19.034,-37.476 -12.802,-37.447 -12.04,-37.447 -19.034,-36.918 -12.802,-36.888 -12.04,-36.888 -19.034,-36.359 -12.802,-36.329 -12.04,-36.329 -19.034,-35.8 -12.802,-35.771 -12.04,-35.771 -19.034,-35.241 -12.802,-35.212 -12.04,-35.212 -19.034,-34.682 -12.802,-34.653 -12.04,-34.653 -19.034,-34.098 -12.802,-34.094 -12.04,-34.094 -18.161,-28.709 -18.923,-28.677 -12.04,-28.658 -12.802,-28.626 -18.161,-28.169 -18.923,-28.143 -12.04,-28.118 -12.802,-28.092 -18.161,-27.61 -18.923,-27.584 -12.04,-27.559 -12.802,-27.534 -18.161,-27.051 -18.923,-27.026 -12.04,-27 -12.802,-26.975 -18.161,-26.492 -18.923,-26.467 -12.04,-26.441 -12.802,-26.416 -18.161,-25.933 -18.923,-25.908 -12.04,-25.883 -12.802,-25.857 -18.161,-25.375 -18.923,-25.349 -12.04,-25.324 -12.802,-25.298 -18.161,-24.816 -18.923,-24.79 -12.04,-24.765 -12.802,-24.74 -18.161,-24.257 -18.923,-24.232 -12.04,-24.206 -12.802,-24.181
NetC8_2: C8.2 C106.1 | length 34.7
  Top Layer w1.524: C8.2@-163.195,-8.163 C106.1@-163.195,3.4
  Layer 3 w1.524: C8.2@-163.195,-8.163 C106.1@-163.195,3.4
  Bottom Layer w1.524: C8.2@-163.195,-8.163 C106.1@-163.195,3.4
NetC18_1: C18.1 R3.1 R5.2 U3.3 | length 5.1
  Top Layer w0.254: U3.3@-9.146,29.036 -5.678,29.036 R5.2@-5.649,29.008 R3.1@-5.649,27.404
NetC25_2: C25.2 R14.1 R19.2 U2.4 | length 4.9
  Top Layer w0.254: R14.1@-20.071,45.145 -20.083,45.157 C25.2@-20.083,46.228 -20.036,46.275 v1(-20.036,47.074)
  Bottom Layer w0.254: v1(-20.036,47.074) -20.034,47.076 -18.548,47.076 U2.4@-18.546,47.078 -18.546,48.503 R19.2@-18.508,48.541
NetC40_1: C40.1 R18.2 U4.2 | length 4
  Top Layer w0.508: R18.2@-152.978,31.411 U4.2@-148.928,31.411
NetC40_2: C40.2 R24.2 U4.3 | length 4.2
  Top Layer w0.508: R24.2@-152.978,29.811 -152.94,29.849 -151.015,29.849 C40.2@-150.978,29.886 -150.978,29.911 -150.748,30.141 U4.3@-148.928,30.141
NetC42_1: C42.1 R21.2 R25.2 U2.3 | length 4.3
  Bottom Layer w0.254: C42.1@-22.786,45.517 R25.2@-22.786,46.8 R21.2@-22.786,47.991 -22.613,47.818 -22.236,47.818 -21.496,47.078 U2.3@-21.296,47.078
NetC73_1: C73.1 R20.1 R27.2 U5.2 | length 18.1
  Top Layer w0.508: v1(-153.67,24.028) -152.858,24.028 R27.2@-152.835,24.005 U5.2@-149.57,24.005
  Layer 3 w0.508: v1(-155.778,12.04) -155.778,21.92 v1(-153.67,24.028)
  Bottom Layer w0.508: v1(-155.778,12.04) -155.778,10.974 R20.1@-155.716,10.911
NetC78_2: C78.2 J5.31 R86.2 | length 4.6
  Top Layer w0.254: R86.2@-22.683,43.974 C78.2@-22.683,42.754 -22.583,42.754 -22.271,42.442 J5.31@-22.271,39.648
NetC79_1: C79.1 J5.25 R84.2 | length 4.4
  Top Layer w0.254: R84.2@-20.071,43.974 -20.071,42.766 -20.056,42.766 -19.871,42.581 J5.25@-19.871,39.648
NetC80_1: C80.1 J5.20 R23.1 | length 4.6
  Top Layer w0.254: J5.20@-17.471,36.248 -17.396,36.173 -17.396,33.271 -17.223,33.098 C80.1@-17.146,33.098 R23.1@-17.146,31.839
NetC81_1: C81.1 J5.30 R76.1 | length 4.4
  Top Layer w0.254: J5.30@-21.471,36.248 -21.471,31.878 R76.1@-21.445,31.851
NetC82_1: C82.1 J5.71 R28.1 | length 5.1
  Top Layer w0.254: R28.1@-42.399,43.393 C82.1@-41.175,43.393 -41.175,42.693 -41.488,42.38 -41.488,39.665 J5.71@-41.471,39.648
NetC83_1: C83.1 J5.73 R29.1 | length 6
  Top Layer w0.254: C83.1@-44.195,44.543 R29.1@-44.195,43.273 -44.139,43.217 -43.562,43.217 -42.334,41.989 -42.334,39.711 J5.73@-42.271,39.648
NetC84_1: C84.1 J5.86 R97.2 | length 4.9
  Top Layer w0.254: R97.2@-48.321,32.634 C84.1@-47.071,32.634 J5.86@-47.071,36.248
NetC85_1: C85.1 J5.88 R98.2 | length 6
  Top Layer w0.254: R98.2@-50.648,32.634 C85.1@-49.471,32.634 -49.471,33.27 -49.159,33.581 -48.176,33.581 -47.871,33.887 J5.88@-47.871,36.248
NetC88_1: C88.1 J5.103 R101.2 | length 5.1
  Top Layer w0.254: J5.103@-54.271,39.648 -54.271,42.895 -53.873,43.293 R101.2@-53.873,43.393 ; R101.2@-53.798,43.318 C88.1@-52.569,43.318
NetC89_1: C89.1 J5.105 R102.2 | length 5
  Top Layer w0.254: R102.2@-55.199,44.58 C89.1@-55.199,43.33 -55.071,43.202 J5.105@-55.071,39.648
NetC90_1: C90.1 R104.1 U8.4 | length 3.5
  Top Layer w0.508: C90.1@-151.003,40.035 -151.003,41.074 -150.903,41.074 -150.829,41.001 U8.4@-148.552,41.001
NetC91_1: C91.1 R31.1 U8.3 | length 3.8
  Top Layer w0.508: C91.1@-150.995,43.63 -151.01,43.615 -151.01,42.376 R31.1@-151.026,42.36 -150.016,42.36 -149.927,42.271 U8.3@-148.552,42.271
NetC94_1: C94.1 R105.2 U8.12 | length 3.6
  Top Layer w0.508: U8.12@-138.802,39.731 R105.2@-136.768,39.731 -136.755,39.718 -136.755,38.236 C94.1@-136.742,38.224
NetC96_1: C96.1 C100.1 R70.2 U6.5 | length 5.1
  Bottom Layer w0.254: U6.5@1.241,29.692 2.537,29.692 2.738,29.49 C96.1@2.738,29.39 C96.1@2.738,29.338 ; C100.1@2.738,27.93 C96.1@2.738,29.338 ; R70.2@4.462,28.817 4.114,29.165 2.911,29.165 C96.1@2.738,29.338
NetC96_2: C96.2 C99.1 R72.2 U6.4 | length 4.8
  Bottom Layer w0.254: U6.4@1.241,30.342 2.565,30.342 2.738,30.515 C96.2@2.738,30.59 2.841,30.693 R72.2@4.462,30.693 ; C99.1@2.703,31.962 2.738,31.927 2.738,30.625 C96.2@2.721,30.608
  Bottom Layer w0.508: C96.2@2.721,30.608 C96.2@2.738,30.59
NetC101_2: C101.2 C109.1 | length 34.9
  Top Layer w1.27: C101.2@-163.093,-34.722 C101.2@-163.068,-34.747 ; C109.1@-163.068,-46.33 C109.1@-163.043,-46.355
  Top Layer w1.524: C109.1@-163.068,-46.33 C101.2@-163.068,-34.747
  Layer 3 w1.524: C101.2@-163.093,-34.722 -163.093,-46.304 C109.1@-163.043,-46.355
  Bottom Layer w1.524: C109.1@-163.093,-46.304 C101.2@-163.093,-34.722
NetC103_2: C103.2 J5.34 R89.2 | length 4.7
  Top Layer w0.254: C103.2@-24.492,32.966 -23.121,32.966 R89.2@-23.086,32.931 -23.078,32.939 -23.078,36.24 J5.34@-23.071,36.248
NetC104_2: C104.2 C107.1 C108.2 R32.1 R33.1 R35.1 R36.1 | length 15
  Top Layer w0.254: R32.1@18.771,31.441 18.771,31.466 18.423,31.814 18.398,31.814 18.331,31.881 C107.1@17.271,31.881 16.148,31.881 15.625,32.404 R33.1@15.625,32.481 15.625,32.756 14.26,34.122 14.26,37.351 15.625,38.716 R36.1@15.625,38.991 15.625,39.068 16.148,39.591 C108.2@17.271,39.591 17.271,39.691 17.609,40.029 R35.1@18.771,40.029 R35.1@18.771,40.004
NetC110_1: C110.1 J5.23 R85.1 | length 4.6
  Top Layer w0.254: J5.23@-19.071,39.648 -19.071,42.38 -18.697,42.754 C110.1@-18.597,42.754 R85.1@-18.597,43.989
NetC112_1: C112.1 J5.14 R22.1 | length 4.6
  Top Layer w0.254: J5.14@-15.071,36.248 -15.071,33.4 -14.769,33.098 C112.1@-14.669,33.098 R22.1@-14.669,31.851
NetJ4_4: J4.4 R74.2 | length 2.6
  Top Layer w0.508: J4.4@-179.191,33.53 -179.152,33.492 -176.664,33.492 R74.2@-176.625,33.453
NetJ5_69: J5.69 R26.2 | length 4.2
  Top Layer w0.254: J5.69@-40.671,39.648 -40.671,42.353 -39.706,43.318 R26.2@-39.606,43.318
NetJ5_72: J5.72 R30.1 | length 3.3
  Top Layer w0.254: v1(-41.488,33.828) -41.479,33.836 -41.479,36.239 J5.72@-41.471,36.248
  Bottom Layer w0.254: v1(-41.488,33.828) R30.1@-41.488,34.722
NetL2_1: L2.1 U9.6 | length 2.4
  Top Layer w0.254: v1(7.95,36.22) 7.95,36.927 L2.1@8.037,37.014
  Bottom Layer w0.254: U9.6@6.427,36.089 7.752,36.089 7.884,36.22 v1(7.95,36.22)
NetL2_2: L2.2 U9.7 | length 2.4
  Top Layer w0.254: v1(7.962,35.265) 7.962,34.589 L2.2@8.037,34.514
  Bottom Layer w0.254: U9.7@6.427,35.439 7.722,35.439 7.896,35.265 v1(7.962,35.265)
NetL2_3: L2.3 R33.2 | length 2.1
  Top Layer w0.254: L2.3@12.587,34.514 12.587,32.619 R33.2@12.725,32.481
NetL2_4: L2.4 R36.2 | length 2
  Top Layer w0.254: L2.4@12.587,37.014 12.725,37.152 R36.2@12.725,38.991
NetL7_1: L7.1 U16.7 | length 3.1
  Top Layer w0.254: L7.1@-44.175,30.81 -44.175,29.76 -43.199,28.784 U16.7@-43.199,28.119
NetR1_1: pad.2@-15.9,-2.1 pad.2@-15.85,-12.954 R1.1 R2.1 R4.1 R7.1 R16.1 U1.8 | length 31.7
  Top Layer w0.254: v1(-20.557,27.567) U1.8@-20.557,28.113
  Top Layer w0.508: R1.1@-10.468,1.65 -10.468,2.507 -10.072,2.903 v1(-9.56,2.903)
  Bottom Layer w0.508: v1(-20.557,27.567) -20.557,25.695 -9.56,14.697 v1(-9.56,2.903)
  other v1: -19.111,-15.208 -12.319,-15.12 -13.081,-15.088 -19.111,-14.649 -12.319,-14.58 -13.081,-14.554 -19.111,-14.09 -12.319,-14.021 -13.081,-13.995 -19.111,-13.532 -12.319,-13.462 -13.081,-13.437 -19.111,-12.973 -12.319,-12.903 -13.081,-12.878 -19.111,-12.414 -12.319,-12.344 -13.081,-12.319 -19.111,-11.855 -12.319,-11.786 -13.081,-11.76 -19.111,-11.271 -12.319,-11.227 -13.081,-11.201 -12.319,-10.668 -13.081,-10.643 -19.1,-4.261 -12.319,-4.147 -13.081,-4.115 -19.1,-3.702 -12.319,-3.607 -13.081,-3.581 -19.1,-3.143 -12.319,-3.048 -13.081,-3.023 -19.1,-2.584 -12.319,-2.489 -13.081,-2.464 -19.1,-2.025 -12.319,-1.93 -13.081,-1.905 -19.1,-1.467 -12.319,-1.372 -13.081,-1.346 -19.1,-0.908 -12.319,-0.813 -13.081,-0.787 -19.1,-0.324 -12.319,-0.254 -13.081,-0.229 -12.319,0.305 -13.081,0.33
NetR6_2: R6.2 U10.7 | length 4.1
  Top Layer w0.508: R6.2@-127.33,9.716 -127.33,9.691 -127.109,9.47 -127.084,9.47 -126.667,9.053 -126.667,7.254 -126.954,6.967 -126.954,6.089 U10.7@-127,6.043
NetR10_1: R10.1 U10.8 | length 2.1
  Top Layer w0.508: U10.8@-128.27,6.043 -128.27,7.543 -127.889,7.925 R10.1@-127.864,7.925
NetR15_1: R15.1 R17.2 | length 2
  Bottom Layer w0.508: R15.1@-155.716,1.143 R17.2@-155.716,3.146
NetR17_1: R17.1 R20.2 | length 2
  Bottom Layer w0.508: R17.1@-155.716,6.046 R20.2@-155.716,8.011
NetR19_1: R19.1 U4.6 | length 125.9
  Top Layer w0.508: U4.6@-138.028,30.141 -138.02,30.15 v1(-136.804,30.15)
  Layer 3 w0.508: v1(-136.804,30.15) -102.718,30.15 -84.353,48.514 v1(-20.505,48.514)
  Bottom Layer w0.508: v1(-20.505,48.514) -19.735,48.514 R19.1@-19.708,48.541
NetR21_1: R21.1 U4.7 | length 123.8
  Top Layer w0.508: U4.7@-138.028,31.411 v1(-136.804,31.411)
  Layer 2 w0.508: v1(-136.804,31.411) -135.958,31.411 -134.747,30.201 -102.692,30.201 -84.379,48.514 -24.841,48.514 v1(-24.028,49.327)
  Bottom Layer w0.508: v1(-24.028,49.327) -24.028,48.033 R21.1@-23.986,47.991
NetR34_2: R34.2 U9.8 | length 1.8
  Bottom Layer w0.254: R34.2@6.377,32.996 6.427,33.046 U9.8@6.427,34.789
NetT1_1: pad.2@-122.777,-16.645 U10.2
  other v1: -124.282,-11.481 -123.698,-11.481 -123.139,-11.481 -122.58,-11.481 -122.022,-11.481 -121.463,-11.481 -124.485,-10.822 -123.901,-10.822 -123.342,-10.822 -122.784,-10.822 -122.225,-10.822 -121.666,-10.822
PGND: 1.1 C11.2 C12.2 C13.2 C30.2 C31.2 C35.2 C47.2 C73.2 C75.1 C76.2 C77.2 C86.2 C90.2 C91.2 C105.2 C106.2 C109.2 C141.2 J4.5 J7.2 J8.2 PGND1.1 PGND2.1 PGND.1 R8.2 R9.2 R18.1 R27.1 U4.4 U5.3 U5.4 U7.3 U7.5 U7.7 U8.2 U8.8 | length 42.9
  Top Layer w0.254: C77.2@-161.786,44.784 -161.394,44.392 -159.884,44.392 -159.761,44.269 v2(-159.761,44.023) U7.7@-159.211,44.023 U7.5@-159.211,43.048 ; U7.3@-159.861,44.998 -159.848,44.985 -159.848,44.396 U7.7@-159.618,44.166 ; C76.2@-157.306,43.538 -157.156,43.388 -156.17,43.388 C75.1@-155.822,43.04
  Top Layer w0.508: v2(-158.661,44.023) -158.464,43.826 C76.2@-157.306,43.826 ; v1(-155.328,31.411) R18.1@-154.578,31.411 ; C47.2@-153.085,25.601 -153.06,25.601 -152.585,26.076 C35.2@-152.585,27.086 v1(-152.585,27.636) ; v1(-152.896,46.681) -152.255,46.681 C86.2@-152.171,46.597 ; v1(-152.853,40.035) C90.2@-152.41,40.035 ; v1(-152.845,43.63) C91.2@-152.195,43.63 ; v1(-152.835,21.655) R27.1@-152.835,22.405 ; C30.2@-152.503,33.109 -152.503,34.226 -152.203,34.526 C31.2@-152.103,34.526 ; C86.2@-152.171,46.622 C86.2@-152.171,46.597 ; v1(-151.31,22.205) C73.2@-151.31,22.855 ; C141.2@-150.687,46.215 -150.687,46.315 -150.733,46.361 -150.833,46.361 -151.069,46.597 C86.2@-152.171,46.597 ; v1(-150.055,21.454) U5.4@-148.879,21.454 U5.3@-148.879,22.724 ; v1(-149.727,43.541) U8.2@-148.552,43.541 ; v1(-149.665,35.921) U8.8@-148.552,35.921 ; v1(-148.971,28.296) -148.971,28.828 U4.4@-148.928,28.871
  Layer 3 w0.508: v1(-164.168,17.052) -164.168,19.22 -154.254,29.134 -154.254,30.338 v1(-155.328,31.411)
  Bottom Layer w0.508: v1(-164.168,17.052) R8.2@-163.218,17.052
  other v1: -165.234,-57.119 -164.675,-57.119 -164.116,-57.119 -163.557,-57.119 -162.998,-57.119 -162.44,-57.119 -161.881,-57.119 -161.322,-57.119 -160.789,-57.119 -165.208,-56.357 -164.649,-56.357 -164.091,-56.357 -163.532,-56.357 -162.973,-56.357 -162.414,-56.357 -161.855,-56.357 -161.297,-56.357 -160.756,-56.357 -130.072,-47.064 -129.532,-47.064 -128.973,-47.064 -128.414,-47.064 -127.855,-47.064 -127.296,-47.064 -126.738,-47.064 -126.179,-47.064 -125.62,-47.064 -130.04,-46.302 -129.506,-46.302 -128.947,-46.302 -128.389,-46.302 -127.83,-46.302 -127.271,-46.302 -126.712,-46.302 -126.153,-46.302 -125.595,-46.302 -150.368,-32.182 -150.368,-31.623 -150.368,-31.064 -137.001,-30.916 -111.404,-30.785 -150.368,-30.505 -137.001,-30.357 -111.404,-30.226 -150.368,-29.947 -137.001,-29.799 -111.404,-29.667 -150.368,-29.388 -137.001,-29.24 -111.404,-29.108 -150.368,-28.829 -137.001,-28.681 -111.404,-28.55 -150.368,-28.245 -137.001,-28.122 -111.404,-27.991 -137.001,-27.563 -111.404,-27.432 -137.001,-26.979 -111.404,-26.848 -150.399,-25.395 -150.399,-24.836 -150.399,-24.277 -150.399,-23.719 -150.399,-23.16 -150.399,-22.601 -150.399,-22.042 -150.399,-21.458 -173.99,-1.43 -174.752,-1.397 -173.99,-0.889 -174.752,-0.864 -173.99,-0.33 -174.752,-0.305 -173.99,0.229 -174.752,0.254 -173.99,0.787 -174.752,0.813 -173.99,1.346 -174.752,1.372 -173.99,1.905 -174.752,1.93 -173.99,2.464 -174.752,2.489 -173.99,3.023 -174.752,3.048 -183.158,22.257 -183.92,22.282 -183.158,22.816 -183.92,22.841 -183.158,23.375 -183.92,23.4 -183.158,23.933 -183.92,23.959 -183.158,24.492 -183.92,24.518 -183.158,25.051 -183.92,25.076 -183.158,25.61 -183.92,25.635 -183.158,26.169 -183.92,26.194 -183.158,26.702 -183.92,26.735 -152.503,33.976 -176.78,49.501 -176.221,49.501 -175.662,49.501 -175.103,49.501 -174.544,49.501 -173.986,49.501 -173.427,49.501 -172.868,49.501 -172.335,49.501 -176.754,50.263 -176.195,50.263 -175.637,50.263 -175.078,50.263 -174.519,50.263 -173.96,50.263 -173.401,50.263 -172.843,50.263 -172.302,50.263
RTN: pad.2@-183.261,14.835 R8.1 R9.1 R24.1 | length 18
  Top Layer w0.508: v1(-155.328,29.811) R24.1@-154.578,29.811
  Layer 3 w0.508: v1(-165.352,17.007) -165.352,20.328 -155.869,29.811 v1(-155.328,29.811)
  other v1: -184.716,9.622 -184.175,9.622 -183.617,9.622 -183.058,9.622 -182.499,9.622 -181.94,9.622 -184.683,10.384 -184.15,10.384 -183.591,10.384 -183.032,10.384 -182.474,10.384 -181.915,10.384 -167.667,13.539 -168.429,13.572 -167.667,14.08 -168.429,14.105 -167.667,14.639 -168.429,14.664 -167.667,15.198 -168.429,15.223 -167.667,15.756 -168.429,15.782 -167.667,16.315 -168.429,16.341 -167.667,16.874 -168.429,16.899 -167.667,17.433 -168.429,17.458 -167.667,17.992 -168.429,18.017
SCI_RX0_Pri: J4.3 U8.5 | length 32.2
  Top Layer w0.508: J4.3@-179.191,36.07 -179.154,36.107 -153.151,36.107 -149.574,39.685 -148.598,39.685 U8.5@-148.552,39.731
SCI_RX0_Sec: R29.2 U8.13 | length 98.2
  Top Layer w0.508: U8.13@-138.802,41.001 -138.796,40.996 -137.631,40.996 -97.594,40.996 -90.711,47.879 -50.927,47.879 -46.321,43.273 -45.541,43.273 R29.2@-45.395,43.273
SCI_RXCLK_Sec: R28.2 U8.14 | length 101.4
  Top Layer w0.508: U8.14@-138.802,42.271 -137.631,42.271 -98.217,42.271 -91.491,48.997 -46.177,48.997 -42.445,45.264 -42.445,44.639 R28.2@-42.399,44.593
SCI_TX0_Pri: J4.2 R104.2 | length 28
  Top Layer w0.508: J4.2@-179.191,38.61 -179.154,38.647 -156.164,38.647 -153.73,41.082 R104.2@-152.21,41.082
SCI_TX0_Sec: J5.75 R105.1 | length 99.7
  Top Layer w0.254: -47.473,42.545 -43.697,42.545 -43.137,41.986 -43.137,39.714 J5.75@-43.071,39.648
  Top Layer w0.508: R105.1@-135.568,39.731 -97.023,39.731 -89.967,46.787 -51.714,46.787 -47.473,42.545
SCI_TXCLK_Pri: J4.1 R31.2 | length 27.6
  Top Layer w0.508: J4.1@-179.191,41.15 J4.1@-178.872,40.832 ; J4.1@-178.872,41.187 -155.369,41.187 -154.196,42.36 R31.2@-152.226,42.36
